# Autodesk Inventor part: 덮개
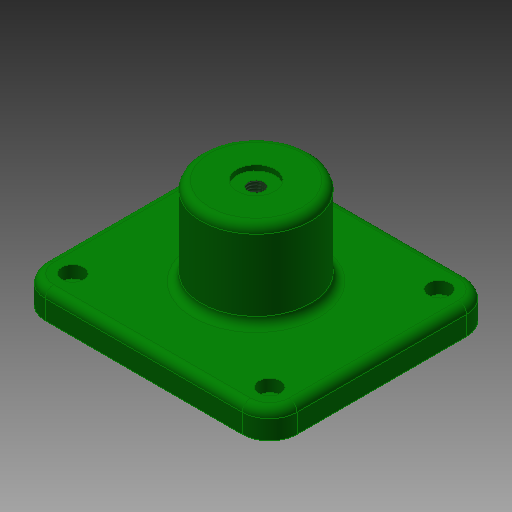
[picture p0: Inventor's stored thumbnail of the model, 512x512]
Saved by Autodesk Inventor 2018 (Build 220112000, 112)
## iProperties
Created: 2017-08
Part Number: 덮개
Material: 알루미늄 6061
Document SubType Name: Modeling
Designer: mduedu
Density: 1 g/cm^3
Appearance: 진녹색
Author: mduedu
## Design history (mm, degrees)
sketch "스케치1"
  geometry: L1 (46, -41)-(-46, -41); L2 (-46, -41)-(-46, 41); L3 (-46, 41)-(46, 41); L4 (46, 41)-(46, -41); 1 further point
  constraints: 8 end point, 2 parallel, 1 horizontal, 1 perpendicular
  dimensions: "d0" = 92 distance of L2.end L3.end; "d2" = 82 distance of L1.end L2.end; "d3" = 41 distance from line of L3 point (0, 0) (= 0.5 x d2); "d4" = 46 distance from line of point (0, 0) L4 (= 0.5 x d0)
extrude "돌출1" new body sketch "스케치1" distance "d5" = 10; taper "d6" = 0 deg
sketch "스케치2"
  geometry: C1 r 20 at (0, 0); 1 further point
  constraints: 1 centre point, 1 coincident
  dimensions: "d55" = 40 diameter of C1
extrude "돌출2" join sketch "스케치2" distance "d9" = 32; taper "d10" = 0 deg
sketch "스케치3"
  geometry: L1 (-26, -26)-(26, -26); L2 (26, -26)-(26, 26); L3 (26, 26)-(-26, 26); L4 (-26, 26)-(-26, -26); L5 (-26, -26)-(26, 26); L6 (26, -26)-(-26, 26); 1 further point
  constraints: 12 end point, 2 midpoint, 2 parallel, 2 perpendicular, 1 horizontal
  dimensions: "d11" = 52 distance of L3.end L2.end
extrude "돌출3" join sketch "스케치3" distance "d12" = 6; taper "d13" = 0 deg
sketch "스케치4"
  geometry: L1 (-17, -17)-(17, -17); L2 (17, -17)-(17, 17); L3 (17, 17)-(-17, 17); L4 (-17, 17)-(-17, -17); L5 (-17, -17)-(17, 17); L6 (17, -17)-(-17, 17); 1 further point
  constraints: 12 end point, 2 midpoint, 2 parallel, 2 perpendicular, 1 horizontal
  dimensions: "d14" = 34 distance of L2.end L3.end
extrude "돌출4" cut sketch "스케치4" distance "d16" = 5; taper "d17" = 0 deg
sketch "스케치5"
  geometry: C1 r 9 at (0, 0); 1 further point
  constraints: 1 centre point, 1 coincident
  dimensions: "d18" = 18 diameter of C1
extrude "돌출5" cut sketch "스케치5" distance "d19" = 34; taper "d20" = 0 deg
sketch "스케치6"
  geometry: 2 further points
  constraints: 1 coincident
hole "구멍1" sketch "스케치6" at (0, 0) diameter "d21" = 5.917; stored, may be unused: countersink angle "d25" = 90 deg, drill point angle "d27" = 118 deg; dims "d22" = 6, "d23" = 14, "d24" = 2, "d26" = 8
fillet "모깎기1" dims "d36" = 10
fillet "모깎기3" dims "d38" = 3
fillet "모깎기4" dims "d39" = 3
fillet "모깎기5" dims "d40" = 3
chamfer "모따기1" distance "d41" = 1; stored, may be unused: second distance "d42" = 2, angle "d43" = 45 deg
fillet "모깎기6" dims "d44" = 3
fillet "모깎기7" dims "d45" = 3
fillet "모깎기8" dims "d46" = 3
sketch "스케치8"
  geometry: A1 r 10 centre (-36, -31) between (-46, -31) and (-36, -41) reference; A2 r 10 centre (-36, 31) between (-36, 41) and (-46, 31) reference; A3 r 10 centre (36, 31) between (46, 31) and (36, 41) reference; A4 r 10 centre (36, -31) between (36, -41) and (46, -31) reference; 5 further points
  constraints: 4 coincident
sketch "스케치9"
  geometry: 4 further points
  constraints: 4 other
hole "구멍3" sketch "스케치9" at (-36, -31), (-36, 31), (36, 31), (36, -31) diameter "d48" = 4.5; stored, may be unused: countersink angle "d52" = 90 deg, drill point angle "d54" = 0 deg; dims "d49" = 6, "d50" = 8, "d51" = 4.6, "d53" = 8
node "솔리드1"
